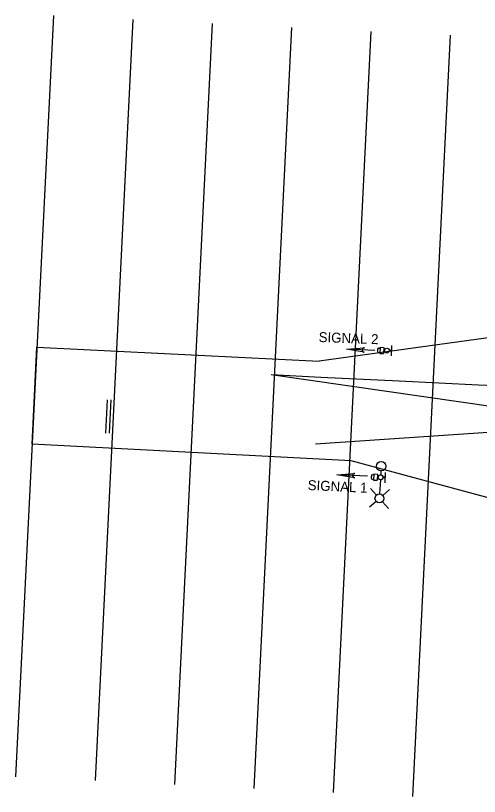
# Model space of a CAD drawing. Extents: x 223098 to 226975, y 386666 to 387582.
# Drawn here: x 223602.5 to 223748.4, y 387145.9 to 387391.8 of the extents above; entities that cross this region are included whole.
import ezdxf

# ---------------------------------------------------------------- set-up
doc = ezdxf.new("R2010")
doc.units = 0
for name, color, linetype in [('Default', 7, 'Continuous'), ('DR_X_Erosion_Control', 7, 'Continuous'), ('PF_X_Ground_Line', 7, 'Continuous'), ('PV_X_EOP', 7, 'Continuous'), ('RW_X_CL_100_Distances', 7, 'Continuous'), ('RW_X_CL_100_Stations', 7, 'Continuous')]:
    doc.layers.add(name, color=color, linetype=linetype)

msp = doc.modelspace()

# ---------------------------------------------------------------- linework, layer by layer
at = {"layer": 'Default'}
for p, q in [((223614.41, 387391.8), (223602.52, 387152.09)), ((223639.38, 387390.56), (223627.49, 387150.85)), ((223664.35, 387389.32), (223652.46, 387149.61)), ((223689.32, 387388.08), (223677.43, 387148.38)), ((223714.29, 387386.84), (223702.4, 387147.14)), ((223739.26, 387385.6), (223727.37, 387145.9))]:
    msp.add_line(p, q, dxfattribs=at)
at = {"layer": 'DR_X_Erosion_Control'}
msp.add_line((223784.61, 387295.04), (223698.01, 387282.93), dxfattribs=at)
msp.add_lwpolyline([(223757.07, 387238.34), (223708.05, 387251.57), (223607.71, 387256.78), (223609.23, 387287.33), (223698.01, 387282.93)], dxfattribs=at)
at = {"layer": 'PF_X_Ground_Line'}
msp.add_line((223696.83, 387256.97), (223841.31, 387266.73), dxfattribs=at)
msp.add_lwpolyline([(223783.77, 387273.83), (223772.91, 387274.33), (223748.15, 387275.45), (223723.16, 387276.66), (223698.57, 387277.87), (223682.89, 387278.67)], dxfattribs=at)
at = {"layer": 'PV_X_EOP'}
for p, q in [((223630.91, 387260.28), (223631.44, 387270.8)), ((223632.44, 387270.76), (223631.91, 387260.24))]:
    msp.add_line(p, q, dxfattribs=at)
at = {"layer": 'RW_X_CL_100_Distances'}
msp.add_line((223841.11, 387255.73), (223682.89, 387278.67), dxfattribs=at)
at = {"layer": 'RW_X_CL_100_Stations'}
for p, q in [((223706.6, 387286.71), (223712.25, 387287.19)), ((223715.54, 387286.36), (223706.6, 387286.71)), ((223712.2, 387285.79), (223706.6, 387286.71)), ((223716.69, 387287.11), (223717.17, 387287.09)), ((223717.19, 387287.34), (223717.12, 387285.4)), ((223717.19, 387287.34), (223718.34, 387287.29)), ((223718.34, 387287.29), (223718.26, 387285.36)), ((223718.57, 387286.44), (223718.3, 387286.45)), ((223720.78, 387287.86), (223720.66, 387284.62)), ((223716.64, 387285.67), (223717.12, 387285.65)), ((223717.12, 387285.4), (223718.26, 387285.36)), ((223718.56, 387286.2), (223718.3, 387286.21)), ((223720.72, 387286.12), (223720.05, 387286.14)), ((223720.72, 387286.36), (223720.06, 387286.38)), ((223703.58, 387247.19), (223709.24, 387247.62)), ((223713.23, 387246.73), (223703.58, 387247.19)), ((223709.17, 387246.22), (223703.58, 387247.19)), ((223714.71, 387247.23), (223715.19, 387247.21)), ((223715.21, 387247.46), (223715.12, 387245.52)), ((223715.21, 387247.46), (223716.36, 387247.4)), ((223716.36, 387247.4), (223716.26, 387245.46)), ((223717.43, 387248.4), (223717.36, 387247.14)), ((223718.81, 387247.94), (223718.65, 387244.7)), ((223714.64, 387245.79), (223715.12, 387245.77)), ((223715.12, 387245.52), (223716.26, 387245.46)), ((223716.57, 387246.3), (223716.3, 387246.31)), ((223716.58, 387246.54), (223716.32, 387246.55)), ((223717.28, 387245.63), (223717.03, 387241.14)), ((223718.72, 387246.2), (223718.06, 387246.23)), ((223718.73, 387246.44), (223718.07, 387246.47)), ((223716.02, 387240.79), (223714.15, 387242.87)), ((223718, 387240.68), (223720.09, 387242.55)), ((223715.91, 387238.81), (223713.83, 387236.94)), ((223717.89, 387238.7), (223719.76, 387236.61))]:
    msp.add_line(p, q, dxfattribs=at)
for centre, radius in [((223719.31, 387286.29), 0.757), ((223717.51, 387249.89), 1.5), ((223717.32, 387246.39), 0.757), ((223716.96, 387239.74), 1.4)]:
    msp.add_circle(centre, radius, dxfattribs=at)
for centre, radius, start, end in [((223712.22, 387286.49), 0.702, 87.8034, 267.8034), ((223709.2, 387246.92), 0.703, 87.2126, 267.2126)]:
    msp.add_arc(centre, radius, start, end, dxfattribs=at)
for centre, major_axis in [((223716.66, 387286.39), (0.027, 0.72)), ((223714.68, 387246.51), (0.034, 0.72))]:
    msp.add_ellipse(centre, major_axis=major_axis, ratio=0.45371, start_param=0, end_param=3.141593, dxfattribs=at)

# ---------------------------------------------------------------- texts
for s, rotation, p in [('SIGNAL 2', 357.8034, (223697.79, 387289.02)), ('SIGNAL 1', 357.2126, (223694.33, 387242.41))]:
    msp.add_text(s, height=3.125, rotation=rotation, dxfattribs=at).set_placement(p)

doc.saveas('drawing.dxf')
